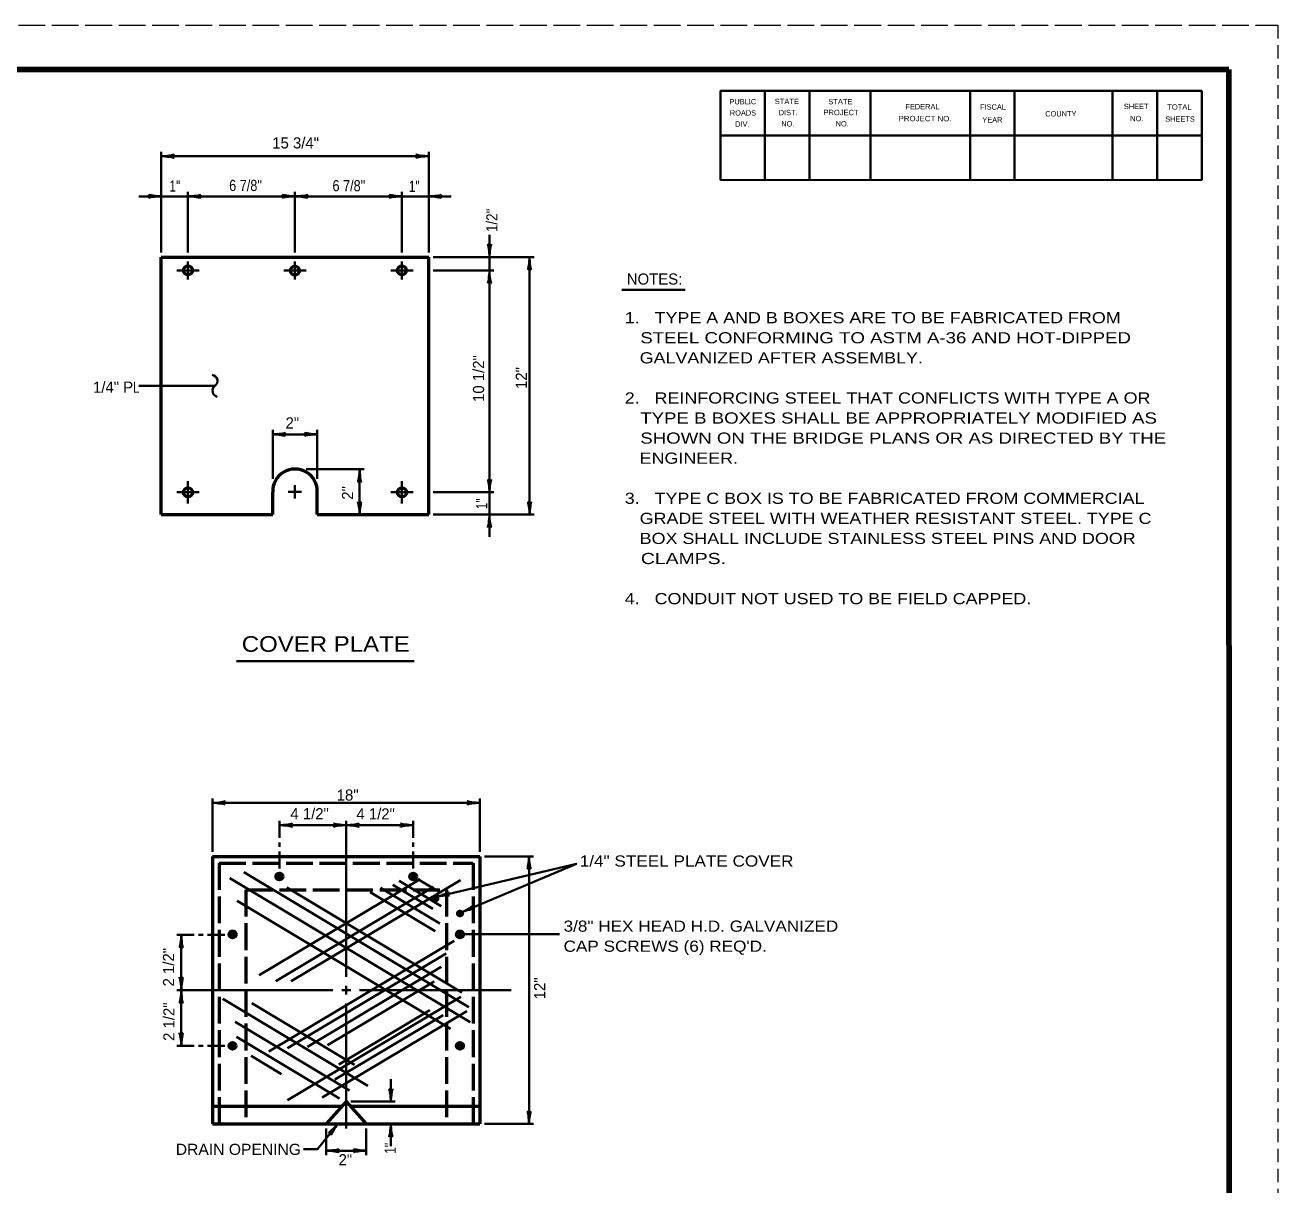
# Model space of a CAD drawing. Extents: x -1 to 679, y 0 to 440.
# Drawn here: x 397.8 to 678.8, y 180.3 to 440.4 of the extents above; entities that cross this region are included whole.
import ezdxf

# ---------------------------------------------------------------- set-up
doc = ezdxf.new("R2010")
doc.units = 0
doc.linetypes.add('LONG_DASHED', pattern=[7.5, 6, -1.5])
doc.linetypes.add('MEDIUM_DASHED', pattern=[4.5, 3, -1.5])
doc.layers.add('1', color=7, linetype='Continuous', lineweight=53)
doc.layers.add('61', color=7, linetype='Continuous', lineweight=35)

msp = doc.modelspace()

# ---------------------------------------------------------------- hatches: boundary and pattern name
at = {"layer": '1'}
for points in [[(455.55, 249.47, 1), (454.05, 249.47, 1)], [(485.552, 249.475, 1), (484.052, 249.475, 1)], [(490.3, 244.477, 1), (489.3, 244.477, 1)], [(495.813, 241.162, 1), (494.813, 241.162, 1)], [(445.061, 236.473, 1), (443.561, 236.473, 1)], [(496.054, 236.473, 1), (494.554, 236.473, 1)], [(445.051, 211.471, 1), (443.551, 211.471, 1)], [(496.053, 211.472, 1), (494.553, 211.472, 1)]]:
    msp.add_hatch(color=256, dxfattribs=at).paths.add_polyline_path(points)

# ---------------------------------------------------------------- linework, layer by layer
at = {"layer": '1', "linetype": 'MEDIUM_DASHED', "lineweight": 13}
msp.add_line((678.783, 440.398), (678.763, 0.378), dxfattribs=at)
at = {"layer": '1', "lineweight": 35}
for p, q in [((428.303, 389.364), (428.303, 411.988)), ((428.303, 410.988), (488.303, 410.988)), ((488.303, 389.364), (488.303, 411.988)), ((434.303, 389.364), (434.303, 402.988)), ((458.303, 402.988), (458.303, 389.364)), ((482.303, 389.364), (482.303, 402.988)), ((511.927, 388.364), (489.303, 388.364)), ((510.927, 388.364), (510.927, 330.614)), ((431.803, 385.364), (436.803, 385.364)), ((434.303, 387.364), (434.303, 383.364)), ((455.803, 385.364), (460.803, 385.364)), ((458.303, 387.364), (458.303, 383.364)), ((479.803, 385.364), (484.803, 385.364)), ((482.303, 387.364), (482.303, 383.364)), ((489.303, 385.364), (502.927, 385.364)), ((501.927, 385.364), (501.927, 335.614)), ((531.59, 381.053), (545.789, 381.053)), ((423.303, 359.489), (440.303, 359.489)), ((453.303, 338.614), (453.303, 349.614)), ((453.303, 348.614), (463.303, 348.614)), ((463.303, 338.614), (463.303, 349.614)), ((473.804, 340.805), (460.804, 340.805)), ((472.804, 340.805), (472.804, 330.614)), ((434.303, 338.114), (434.303, 333.114)), ((482.303, 338.114), (482.303, 333.114)), ((431.803, 335.614), (436.803, 335.614)), ((456.803, 335.717), (459.803, 335.717)), ((458.303, 334.217), (458.303, 337.217)), ((479.803, 335.614), (484.803, 335.614)), ((489.303, 335.614), (502.927, 335.614)), ((511.927, 330.614), (489.303, 330.614)), ((439.803, 254.972), (439.803, 266.972)), ((499.803, 254.972), (499.803, 266.972)), ((439.803, 265.972), (499.803, 265.972)), ((454.835, 261.972), (454.835, 258.096)), ((469.803, 261.972), (469.803, 226.972)), ((484.819, 261.972), (484.819, 258.096)), ((454.835, 257.096), (454.835, 256.096)), ((484.819, 257.096), (484.819, 256.096)), ((454.835, 255.096), (454.835, 251.22)), ((484.819, 255.096), (484.819, 251.225)), ((511.803, 253.972), (500.803, 253.972)), ((510.803, 253.972), (510.803, 193.972)), ((446.842, 250.417), (497.276, 220.156)), ((443.712, 249.087), (497.577, 216.769)), ((486.371, 248.85), (450.295, 227.313)), ((495.432, 248.668), (457.479, 226.009)), ((480.226, 247.587), (489.216, 242.193)), ((481.641, 248.487), (491.06, 242.836)), ((485.887, 248.855), (490.631, 246.009)), ((489.357, 247.139), (453.98, 226.018)), ((456.446, 246.987), (495.733, 223.414)), ((475.167, 245.958), (489.731, 237.22)), ((477.482, 246.901), (490.76, 238.935)), ((445.341, 244.028), (493.203, 215.311)), ((431.803, 236.37), (435.686, 236.37)), ((436.686, 236.37), (437.686, 236.37)), ((438.686, 236.37), (442.568, 236.37)), ((496.054, 236.497), (517.634, 236.497)), ((494.02, 235.014), (452.455, 210.199)), ((492.213, 232.188), (456.658, 210.961)), ((491.092, 229.189), (461.118, 211.294)), ((489.541, 225.934), (465.577, 211.627)), ((469.803, 224.972), (469.803, 222.972)), ((442.158, 222.031), (474.682, 202.517)), ((495.501, 222.504), (456.632, 199.299)), ((468.803, 223.972), (470.803, 223.972)), ((472.803, 223.972), (506.803, 223.972)), ((448.589, 221.088), (471.68, 207.233)), ((496.865, 219.242), (464.437, 199.882)), ((488.549, 219.518), (468.14, 207.334)), ((469.803, 220.972), (469.803, 209.359)), ((444.902, 216.886), (470.566, 201.488)), ((491.547, 218.397), (467.275, 203.906)), ((431.803, 211.514), (435.686, 211.514)), ((436.686, 211.514), (437.686, 211.514)), ((438.686, 211.514), (442.552, 211.514)), ((445.202, 213.499), (468.293, 199.644)), ((448.46, 209.211), (455.259, 205.132)), ((469.803, 209.359), (469.803, 192.972)), ((479.803, 203.972), (479.803, 198.972)), ((470.803, 198.972), (480.803, 198.972)), ((479.803, 193.972), (479.803, 188.972)), ((511.803, 193.972), (500.803, 193.972)), ((465.303, 192.972), (465.303, 186.972)), ((474.303, 192.972), (474.303, 186.972)), ((465.303, 187.972), (474.303, 187.972))]:
    msp.add_line(p, q, dxfattribs=at)
at = {"layer": '1'}
for p, q in [((428.303, 330.614), (428.303, 388.364)), ((428.303, 388.364), (488.303, 388.364)), ((488.303, 330.614), (488.303, 388.364)), ((453.303, 330.614), (453.303, 335.614)), ((463.303, 330.614), (463.303, 335.614)), ((428.303, 330.614), (453.303, 330.614)), ((463.303, 330.614), (488.303, 330.614)), ((439.803, 253.972), (439.803, 193.972)), ((439.803, 253.972), (499.803, 253.972)), ((499.803, 253.972), (499.803, 193.972)), ((439.803, 197.972), (468.903, 197.972)), ((469.803, 198.972), (465.303, 193.972)), ((469.803, 198.972), (474.303, 193.972)), ((470.703, 197.972), (499.803, 197.972))]:
    msp.add_line(p, q, dxfattribs=at)
at = {"layer": '1', "lineweight": 40}
msp.add_line((445.209, 297.728), (485.049, 297.728), dxfattribs=at)
at = {"layer": '1', "linetype": 'LONG_DASHED'}
for p, q in [((441.303, 252.472), (441.303, 193.972)), ((447.303, 246.472), (447.303, 193.972)), ((447.303, 246.472), (492.303, 246.472)), ((492.303, 246.472), (492.303, 193.972))]:
    msp.add_line(p, q, dxfattribs=at)
at = {"layer": '1', "lineweight": 35}
for points in [[(434.303, 401.988), (428.303, 401.988), (423.303, 401.988)], [(434.303, 401.988), (458.303, 401.988), (482.303, 401.988)], [(482.303, 401.988), (488.303, 401.988), (493.303, 401.988)], [(501.927, 385.364), (501.927, 388.364), (501.927, 393.364)], [(501.927, 335.614), (501.927, 330.614), (501.927, 325.614)], [(454.835, 260.972), (469.803, 260.972), (484.819, 260.972)], [(490.056, 244.907), (521.424, 252.315), (495.721, 241.45)], [(432.803, 236.37), (432.803, 223.972), (432.803, 211.514)], [(431.803, 223.972), (447.303, 223.972), (466.803, 223.972)], [(467.892, 193.972), (463.371, 188.298), (460.235, 188.298)]]:
    msp.add_lwpolyline(points, dxfattribs=at)
at = {"layer": '1', "linetype": 'LONG_DASHED'}
msp.add_lwpolyline([(441.303, 252.472), (498.303, 252.472), (498.303, 193.972)], dxfattribs=at)
at = {"layer": '1'}
msp.add_lwpolyline([(439.803, 193.972), (469.803, 193.972), (499.803, 193.972)], dxfattribs=at)
for centre, radius in [((434.289, 385.374), 1), ((458.284, 385.325), 1), ((482.279, 385.374), 1), ((434.296, 335.622), 1), ((482.302, 335.614), 1), ((454.8, 249.47), 0.75), ((484.802, 249.475), 0.75), ((489.8, 244.477), 0.5), ((495.313, 241.162), 0.5), ((444.311, 236.473), 0.75), ((495.304, 236.473), 0.75), ((444.301, 211.471), 0.75), ((495.303, 211.472), 0.75)]:
    msp.add_circle(centre, radius, dxfattribs=at)
at = {"layer": '1', "lineweight": 35}
for centre, radius, start, end in [((439.596, 360.62), 1.333, 301.98498, 84.3636), ((441.24, 358.412), 1.428, 131.05836, 255.29022)]:
    msp.add_arc(centre, radius, start, end, dxfattribs=at)
at = {"layer": '1'}
msp.add_arc((458.302, 335.816), 5.004, 357.68199, 182.31801, dxfattribs=at)
at = {"layer": '1', "lineweight": 40}
for centre, major_axis, ratio, start_param, end_param in [((429.423, 410.776), (-1.756, 0.176), 0.07063, 3.1407148, 5.41811), ((429.423, 410.776), (-1.756, 0.176), 0.07063, 3.1407148, 5.41811), ((429.394, 411.264), (-1.786, -0.156), 0.122415, 0.8963533, 3.1415927), ((429.394, 411.264), (-1.786, -0.156), 0.122415, 0.8963533, 3.1415927), ((487.211, 410.712), (1.786, 0.156), 0.122415, 0.8963533, 3.1415927), ((487.211, 410.712), (1.786, 0.156), 0.122415, 0.8963533, 3.1415927), ((487.182, 411.2), (1.756, -0.176), 0.07063, 3.1407148, 5.41811), ((487.182, 411.2), (1.756, -0.176), 0.07063, 3.1407148, 5.41811), ((427.211, 401.712), (1.786, 0.156), 0.122415, 0.8963533, 3.1415927), ((427.211, 401.712), (1.786, 0.156), 0.122415, 0.8963533, 3.1415927), ((427.182, 402.2), (1.756, -0.176), 0.07063, 3.1407148, 5.41811), ((427.182, 402.2), (1.756, -0.176), 0.07063, 3.1407148, 5.41811), ((435.423, 401.776), (-1.756, 0.176), 0.07063, 3.1407148, 5.41811), ((435.423, 401.776), (-1.756, 0.176), 0.07063, 3.1407148, 5.41811), ((435.394, 402.264), (-1.786, -0.156), 0.122415, 0.8963533, 3.1415927), ((435.394, 402.264), (-1.786, -0.156), 0.122415, 0.8963533, 3.1415927), ((457.211, 401.712), (1.786, 0.156), 0.122415, 0.8963533, 3.1415927), ((457.211, 401.712), (1.786, 0.156), 0.122415, 0.8963533, 3.1415927), ((457.182, 402.2), (1.756, -0.176), 0.07063, 3.1407148, 5.41811), ((457.182, 402.2), (1.756, -0.176), 0.07063, 3.1407148, 5.41811), ((459.423, 401.776), (-1.756, 0.176), 0.07063, 3.1407148, 5.41811), ((459.423, 401.776), (-1.756, 0.176), 0.07063, 3.1407148, 5.41811), ((459.394, 402.264), (-1.786, -0.156), 0.122415, 0.8963533, 3.1415927), ((459.394, 402.264), (-1.786, -0.156), 0.122415, 0.8963533, 3.1415927), ((481.211, 401.712), (1.786, 0.156), 0.122415, 0.8963533, 3.1415927), ((481.211, 401.712), (1.786, 0.156), 0.122415, 0.8963533, 3.1415927), ((481.182, 402.2), (1.756, -0.176), 0.07063, 3.1407148, 5.41811), ((481.182, 402.2), (1.756, -0.176), 0.07063, 3.1407148, 5.41811), ((489.423, 401.776), (-1.756, 0.176), 0.07063, 3.1407148, 5.41811), ((489.423, 401.776), (-1.756, 0.176), 0.07063, 3.1407148, 5.41811), ((489.394, 402.264), (-1.786, -0.156), 0.122415, 0.8963533, 3.1415927), ((489.394, 402.264), (-1.786, -0.156), 0.122415, 0.8963533, 3.1415927), ((501.65, 389.455), (0.156, -1.786), 0.122415, 0.8963533, 3.1415927), ((501.65, 389.455), (0.156, -1.786), 0.122415, 0.8963533, 3.1415927), ((502.138, 389.484), (-0.176, -1.756), 0.07063, 3.1407148, 5.41811), ((502.138, 389.484), (-0.176, -1.756), 0.07063, 3.1407148, 5.41811), ((510.715, 387.243), (0.176, 1.756), 0.07063, 3.1407148, 5.41811), ((510.715, 387.243), (0.176, 1.756), 0.07063, 3.1407148, 5.41811), ((511.203, 387.273), (-0.156, 1.786), 0.122415, 0.8963533, 3.1415927), ((511.203, 387.273), (-0.156, 1.786), 0.122415, 0.8963533, 3.1415927), ((501.715, 384.243), (0.176, 1.756), 0.07063, 3.1407148, 5.41811), ((502.203, 384.273), (-0.156, 1.786), 0.122415, 0.8963533, 3.1415927), ((454.423, 348.402), (-1.756, 0.176), 0.07063, 3.1407148, 5.41811), ((454.394, 348.89), (-1.786, -0.156), 0.122415, 0.8963533, 3.1415927), ((462.211, 348.338), (1.786, 0.156), 0.122415, 0.8963533, 3.1415927), ((462.182, 348.825), (1.756, -0.176), 0.07063, 3.1407148, 5.41811), ((472.593, 339.684), (0.176, 1.756), 0.07063, 3.1407148, 5.41811), ((472.593, 339.684), (0.176, 1.756), 0.07063, 3.1407148, 5.41811), ((473.08, 339.714), (-0.156, 1.786), 0.122415, 0.8963533, 3.1415927), ((473.08, 339.714), (-0.156, 1.786), 0.122415, 0.8963533, 3.1415927), ((501.65, 336.705), (0.156, -1.786), 0.122415, 0.8963533, 3.1415927), ((501.65, 336.705), (0.156, -1.786), 0.122415, 0.8963533, 3.1415927), ((502.138, 336.734), (-0.176, -1.756), 0.07063, 3.1407148, 5.41811), ((502.138, 336.734), (-0.176, -1.756), 0.07063, 3.1407148, 5.41811), ((472.528, 331.705), (0.156, -1.786), 0.122415, 0.8963533, 3.1415927), ((472.528, 331.705), (0.156, -1.786), 0.122415, 0.8963533, 3.1415927), ((473.016, 331.734), (-0.176, -1.756), 0.07063, 3.1407148, 5.41811), ((473.016, 331.734), (-0.176, -1.756), 0.07063, 3.1407148, 5.41811), ((510.65, 331.705), (0.156, -1.786), 0.122415, 0.8963533, 3.1415927), ((510.65, 331.705), (0.156, -1.786), 0.122415, 0.8963533, 3.1415927), ((511.138, 331.734), (-0.176, -1.756), 0.07063, 3.1407148, 5.41811), ((511.138, 331.734), (-0.176, -1.756), 0.07063, 3.1407148, 5.41811), ((501.715, 329.493), (0.176, 1.756), 0.07063, 3.1407148, 5.41811), ((502.203, 329.523), (-0.156, 1.786), 0.122415, 0.8963533, 3.1415927), ((440.894, 266.249), (-1.786, -0.156), 0.122415, 0.8963533, 3.1415927), ((440.894, 266.249), (-1.786, -0.156), 0.122415, 0.8963533, 3.1415927), ((440.924, 265.761), (-1.756, 0.176), 0.07063, 3.1407148, 5.41811), ((440.924, 265.761), (-1.756, 0.176), 0.07063, 3.1407148, 5.41811), ((498.712, 265.696), (1.786, 0.156), 0.122415, 0.8963533, 3.1415927), ((498.683, 266.184), (1.756, -0.176), 0.07063, 3.1407148, 5.41811), ((455.926, 261.249), (-1.786, -0.156), 0.122415, 0.8963533, 3.1415927), ((455.926, 261.249), (-1.786, -0.156), 0.122415, 0.8963533, 3.1415927), ((468.683, 261.184), (1.756, -0.176), 0.07063, 3.1407148, 5.41811), ((468.683, 261.184), (1.756, -0.176), 0.07063, 3.1407148, 5.41811), ((470.894, 261.249), (-1.786, -0.156), 0.122415, 0.8963533, 3.1415927), ((470.894, 261.249), (-1.786, -0.156), 0.122415, 0.8963533, 3.1415927), ((483.698, 261.184), (1.756, -0.176), 0.07063, 3.1407148, 5.41811), ((483.698, 261.184), (1.756, -0.176), 0.07063, 3.1407148, 5.41811), ((455.955, 260.761), (-1.756, 0.176), 0.07063, 3.1407148, 5.41811), ((455.955, 260.761), (-1.756, 0.176), 0.07063, 3.1407148, 5.41811), ((468.712, 260.696), (1.786, 0.156), 0.122415, 0.8963533, 3.1415927), ((468.712, 260.696), (1.786, 0.156), 0.122415, 0.8963533, 3.1415927), ((470.924, 260.761), (-1.756, 0.176), 0.07063, 3.1407148, 5.41811), ((470.924, 260.761), (-1.756, 0.176), 0.07063, 3.1407148, 5.41811), ((483.727, 260.696), (1.786, 0.156), 0.122415, 0.8963533, 3.1415927), ((483.727, 260.696), (1.786, 0.156), 0.122415, 0.8963533, 3.1415927), ((510.592, 252.852), (0.176, 1.756), 0.07063, 3.1407148, 5.41811), ((511.079, 252.881), (-0.156, 1.786), 0.122415, 0.8963533, 3.1415927), ((491.055, 245.426), (-1.702, -0.562), 0.122415, 0.8963533, 3.1415927), ((491.055, 245.426), (-1.702, -0.562), 0.122415, 0.8963533, 3.1415927), ((491.195, 244.958), (1.75, 0.233), 0.07063, 6.2823074, 8.5597026), ((491.195, 244.958), (1.75, 0.233), 0.07063, 6.2823074, 8.5597026), ((496.619, 242.129), (-1.584, -0.839), 0.122415, 0.8963533, 3.1415927), ((496.619, 242.129), (-1.584, -0.839), 0.122415, 0.8963533, 3.1415927), ((496.836, 241.691), (-1.686, -0.522), 0.07063, 3.1407148, 5.41811), ((496.836, 241.691), (-1.686, -0.522), 0.07063, 3.1407148, 5.41811), ((432.592, 235.25), (0.176, 1.756), 0.07063, 3.1407148, 5.41811), ((433.079, 235.279), (-0.156, 1.786), 0.122415, 0.8963533, 3.1415927), ((432.527, 225.064), (0.156, -1.786), 0.122415, 0.8963533, 3.1415927), ((432.527, 225.064), (0.156, -1.786), 0.122415, 0.8963533, 3.1415927), ((433.015, 225.093), (-0.176, -1.756), 0.07063, 3.1407148, 5.41811), ((433.015, 225.093), (-0.176, -1.756), 0.07063, 3.1407148, 5.41811), ((432.592, 222.852), (0.176, 1.756), 0.07063, 3.1407148, 5.41811), ((432.592, 222.852), (0.176, 1.756), 0.07063, 3.1407148, 5.41811), ((433.079, 222.881), (-0.156, 1.786), 0.122415, 0.8963533, 3.1415927), ((433.079, 222.881), (-0.156, 1.786), 0.122415, 0.8963533, 3.1415927), ((432.527, 212.605), (0.156, -1.786), 0.122415, 0.8963533, 3.1415927), ((432.527, 212.605), (0.156, -1.786), 0.122415, 0.8963533, 3.1415927), ((433.015, 212.635), (-0.176, -1.756), 0.07063, 3.1407148, 5.41811), ((433.015, 212.635), (-0.176, -1.756), 0.07063, 3.1407148, 5.41811), ((479.527, 200.064), (0.156, -1.786), 0.122415, 0.8963533, 3.1415927), ((479.527, 200.064), (0.156, -1.786), 0.122415, 0.8963533, 3.1415927), ((480.015, 200.093), (-0.176, -1.756), 0.07063, 3.1407148, 5.41811), ((480.015, 200.093), (-0.176, -1.756), 0.07063, 3.1407148, 5.41811), ((510.527, 195.064), (0.156, -1.786), 0.122415, 0.8963533, 3.1415927), ((511.015, 195.093), (-0.176, -1.756), 0.07063, 3.1407148, 5.41811), ((467.028, 193.228), (1.232, 1.264), 0.07063, 3.1407148, 5.41811), ((467.428, 192.947), (0.991, 1.494), 0.122415, 0.8963533, 3.1415927), ((479.592, 192.852), (0.176, 1.756), 0.07063, 3.1407148, 5.41811), ((479.592, 192.852), (0.176, 1.756), 0.07063, 3.1407148, 5.41811), ((480.079, 192.881), (-0.156, 1.786), 0.122415, 0.8963533, 3.1415927), ((480.079, 192.881), (-0.156, 1.786), 0.122415, 0.8963533, 3.1415927), ((466.394, 188.249), (-1.786, -0.156), 0.122415, 0.8963533, 3.1415927), ((466.394, 188.249), (-1.786, -0.156), 0.122415, 0.8963533, 3.1415927), ((473.183, 188.184), (1.756, -0.176), 0.07063, 3.1407148, 5.41811), ((466.424, 187.761), (-1.756, 0.176), 0.07063, 3.1407148, 5.41811), ((466.424, 187.761), (-1.756, 0.176), 0.07063, 3.1407148, 5.41811), ((473.212, 187.696), (1.786, 0.156), 0.122415, 0.8963533, 3.1415927)]:
    msp.add_ellipse(centre, major_axis=major_axis, ratio=ratio, start_param=start_param, end_param=end_param, dxfattribs=at)
at = {"layer": '61', "linetype": 'LONG_DASHED', "lineweight": 13}
msp.add_line((-1.237, 440.398), (678.783, 440.398), dxfattribs=at)
at = {"layer": '61', "lineweight": 158}
msp.add_line((667.803, 430.398), (667.823, 10.358), dxfattribs=at)
at = {"layer": '61'}
for p, q in [((563.723, 425.638), (563.723, 405.638)), ((573.723, 425.638), (573.723, 405.638)), ((587.403, 425.638), (587.403, 405.638)), ((609.723, 425.638), (609.723, 405.638)), ((619.723, 425.638), (619.723, 405.638)), ((641.703, 425.658), (641.703, 405.658)), ((651.703, 425.658), (651.703, 405.658)), ((661.723, 415.618), (553.703, 415.638))]:
    msp.add_line(p, q, dxfattribs=at)
at = {"layer": '61', "lineweight": 158}
msp.add_lwpolyline([(667.803, 430.398), (28.763, 430.398), (28.763, 10.378)], dxfattribs=at)
at = {"layer": '61'}
for points in [[(661.703, 425.658), (553.723, 425.638), (553.723, 405.638)], [(661.703, 425.658), (661.703, 405.658), (553.723, 405.638)]]:
    msp.add_lwpolyline(points, dxfattribs=at)

# ---------------------------------------------------------------- texts
at = {"layer": '1'}
for s, p in [('15 3/4"', (453.207, 412.716)), ('NOTES:', (532.732, 382.196)), ('1/4" P', (413.014, 357.948)), ('2"', (456.188, 349.923)), ('18"', (467.666, 266.472)), ('4 1/2"', (457.273, 262.288)), ('4 1/2"', (472.083, 262.242)), ('2"', (468.081, 184.69))]:
    msp.add_text(s, height=2.5, dxfattribs=at).set_placement(p)
for s, height, width, p in [('1"', 2.5, 0.8, (430.143, 403.041)), ('6 7/8"', 2.5, 0.85, (443.545, 403.183)), ('6 7/8"', 2.5, 0.85, (466.719, 403.121)), ('1"', 2.5, 0.8, (483.837, 402.981)), ('1.   TYPE A AND B BOXES ARE TO BE FABRICATED FROM', 2.5, 1.2, (532.275, 373.523)), ('   STEEL CONFORMING TO ASTM A-36 AND HOT-DIPPED', 2.5, 1.25, (532.275, 369.023)), ('   GALVANIZED AFTER ASSEMBLY.', 2.5, 1.2, (532.275, 364.523)), ('L', 2.5, 0.75, (422.004, 357.925)), ('2.   REINFORCING STEEL THAT CONFLICTS WITH TYPE A OR', 2.5, 1.2, (532.275, 355.523)), ('   TYPE B BOXES SHALL BE APPROPRIATELY MODIFIED AS', 2.5, 1.25, (532.275, 351.023)), ('   SHOWN ON THE BRIDGE PLANS OR AS DIRECTED BY THE', 2.5, 1.25, (532.275, 346.523)), ('   ENGINEER.', 2.5, 1.2, (532.275, 342.023)), ('3.   TYPE C BOX IS TO BE FABRICATED FROM COMMERCIAL', 2.5, 1.2, (532.275, 333.023)), ('   GRADE STEEL WITH WEATHER RESISTANT STEEL. TYPE C', 2.5, 1.2, (532.275, 328.523)), ('   BOX SHALL INCLUDE STAINLESS STEEL PINS AND DOOR', 2.5, 1.2, (532.275, 324.023)), ('   CLAMPS.', 2.5, 1.3, (532.275, 319.523)), ('4.   CONDUIT NOT USED TO BE FIELD CAPPED.', 2.5, 1.2, (532.275, 310.523)), ('COVER PLATE', 3.5, 1.15, (446.364, 299.852)), ('1/4" STEEL PLATE COVER', 2.5, 1.15, (522.179, 251.683)), ('3/8" HEX HEAD H.D. GALVANIZED', 2.5, 1.15, (518.548, 237.076)), ("CAP SCREWS (6) REQ'D.", 2.5, 1.15, (518.548, 232.576)), ('DRAIN OPENING', 2.5, 1.05, (431.569, 187.023))]:
    msp.add_text(s, height=height, dxfattribs=dict(at, width=width)).set_placement(p)
for s, width, p in [('1/2"', 0.9, (503.717, 393.978)), ('1"', 0.8, (501.425, 331.805)), ('1"', 0.8, (480.907, 187.278))]:
    msp.add_text(s, height=2.5, rotation=90, dxfattribs=dict(at, width=width)).set_placement(p)
for s, p in [('10 1/2"', (500.72, 355.881)), ('12"', (510.329, 358.791)), ('2"', (471.345, 333.955)), ('2 1/2"', (431.189, 224.814)), ('12"', (514.433, 221.921)), ('2 1/2"', (431.276, 212.586))]:
    msp.add_text(s, height=2.5, rotation=90, dxfattribs=at).set_placement(p)
at = {"layer": '61'}
for s, rotation, p in [('PUBLIC', 0.033, (555.763, 422.618)), ('FEDERAL', 0.007, (595.223, 421.498)), ('FISCAL', 359.942, (611.963, 421.438)), ('SHEET', 0.059, (644.223, 421.558)), ('ROADS', 0.124, (555.843, 420.098)), ('DIV.', 359.932, (557.043, 417.598)), ('DIST.', 0.056, (566.803, 420.178)), ('YEAR', 0.105, (612.483, 418.538)), ('COUNTY', 0.069, (626.583, 419.898)), ('SHEETS', 359.959, (653.503, 418.718))]:
    msp.add_text(s, height=1.201, rotation=rotation, dxfattribs=at).set_placement(p)
for s, rotation, width, p in [('STATE', 0.059, 1.05, (565.923, 422.678)), ('STATE', 0.059, 1.05, (577.923, 422.618)), ('TOTAL', 359.926, 1.05, (653.963, 421.418)), ('NO.', 359.852, 0.95, (567.383, 417.658)), ('PROJECT', 359.908, 1.05, (576.843, 420.198)), ('NO.', 0.225, 0.95, (579.583, 417.658)), ('PROJECT NO.', 359.922, 1.1, (593.683, 418.838)), ('NO.', 359.852, 0.95, (645.643, 418.838))]:
    msp.add_text(s, height=1.201, rotation=rotation, dxfattribs=dict(at, width=width)).set_placement(p)

doc.saveas('drawing.dxf')
